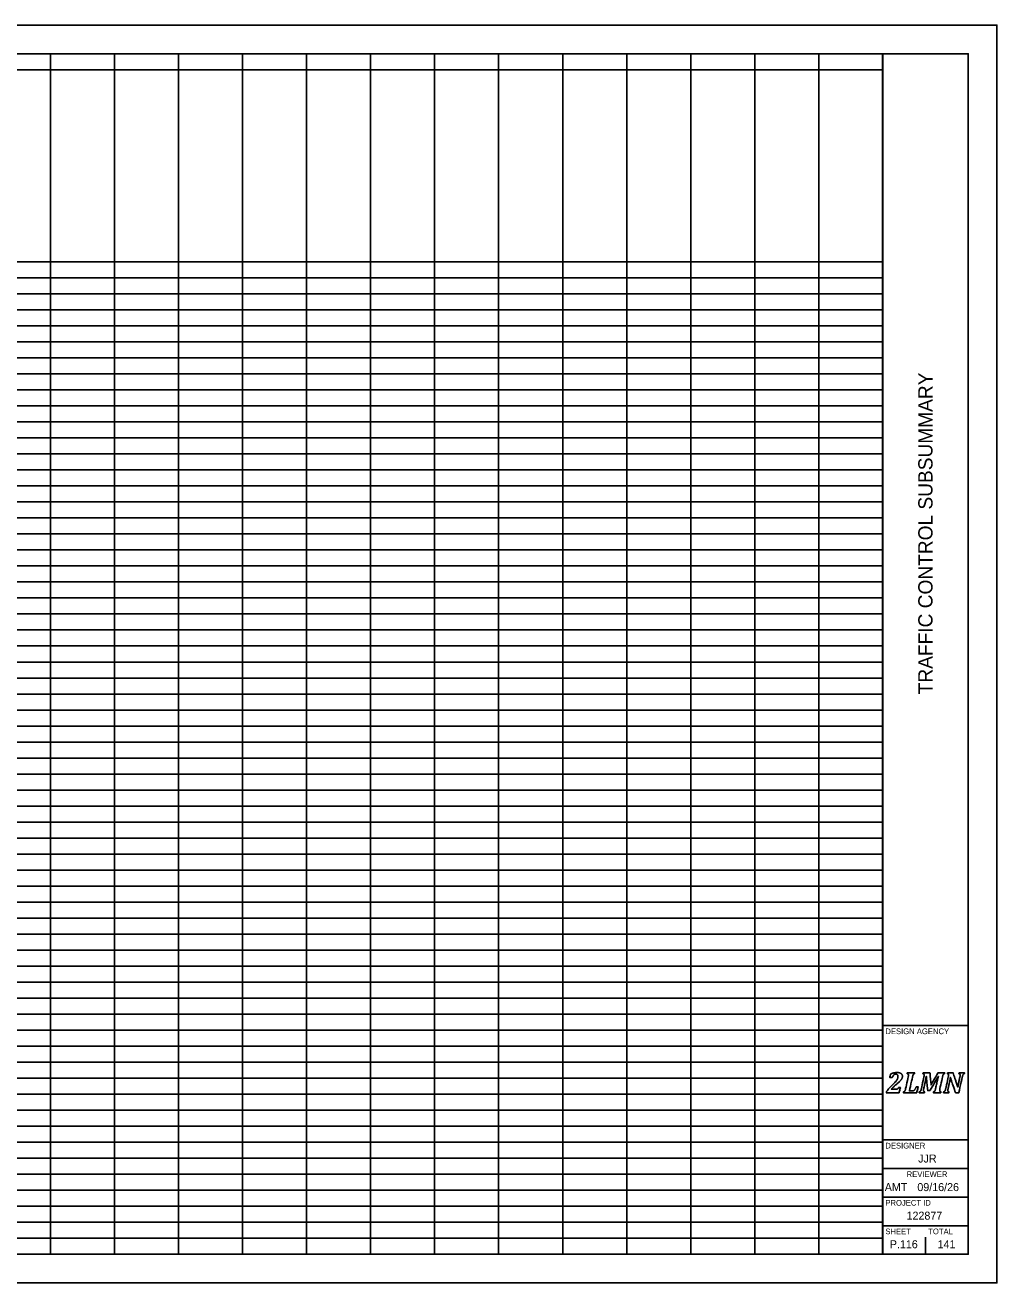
# Model space of a CAD drawing. Extents: x 0 to 34, y 0 to 22.
# Drawn here: x 17 to 34, y 0 to 22 of the extents above; entities that cross this region are included whole.
import ezdxf

# ---------------------------------------------------------------- set-up
doc = ezdxf.new("R2010")
doc.units = 0
for name, color, linetype in [('SH_Border', 7, 'Continuous'), ('SH_Cut_Line', 7, 'Continuous'), ('SH_Data', 7, 'Continuous'), ('SH_Text', 7, 'Continuous')]:
    doc.layers.add(name, color=color, linetype=linetype)

msp = doc.modelspace()

# ---------------------------------------------------------------- linework, layer by layer
at = {"layer": 'SH_Border'}
for p, q in [((32, 0.5), (32, 21.5)), ((32, 4.5), (33.5, 4.5)), ((32, 2.5), (33.5, 2.5)), ((32, 2), (33.5, 2)), ((32, 1.5), (33.5, 1.5)), ((32, 1), (33.5, 1))]:
    msp.add_line(p, q, dxfattribs=at)
msp.add_lwpolyline([(1.5, 21.5), (33.5, 21.5), (33.5, 0.5), (1.5, 0.5)], close=True, dxfattribs=at)
at = {"layer": 'SH_Cut_Line'}
msp.add_lwpolyline([(0, 0), (34, 0), (34, 22), (0, 22)], close=True, dxfattribs=at)
at = {"layer": 'SH_Data'}
for p, q in [((32.75, 3.5), (32.75, 3.5)), ((32.375, 0.675), (32.375, 0.675)), ((32.75, 0.5), (32.75, 0.8))]:
    msp.add_line(p, q, dxfattribs=at)
for points in [[(32.237, 3.388), (32.246, 3.388), (32.253, 3.389), (32.258, 3.39), (32.263, 3.392), (32.267, 3.394), (32.27, 3.397), (32.273, 3.401), (32.277, 3.408), (32.281, 3.417), (32.281, 3.417), (32.312, 3.417), (32.312, 3.417), (32.312, 3.417), (32.29, 3.326), (32.29, 3.326), (32.29, 3.326), (32.066, 3.326), (32.066, 3.326), (32.066, 3.326), (32.069, 3.343), (32.069, 3.343), (32.078, 3.358), (32.091, 3.375), (32.106, 3.394), (32.122, 3.412), (32.144, 3.435), (32.172, 3.462), (32.197, 3.486), (32.217, 3.506), (32.23, 3.521), (32.243, 3.537), (32.253, 3.551), (32.259, 3.566), (32.266, 3.58), (32.269, 3.595), (32.269, 3.61), (32.269, 3.622), (32.266, 3.632), (32.26, 3.64), (32.253, 3.647), (32.245, 3.65), (32.234, 3.65), (32.22, 3.65), (32.208, 3.646), (32.198, 3.636), (32.188, 3.627), (32.18, 3.613), (32.172, 3.593), (32.172, 3.593), (32.126, 3.593), (32.126, 3.593), (32.126, 3.593), (32.14, 3.654), (32.14, 3.654), (32.166, 3.663), (32.188, 3.669), (32.205, 3.673), (32.223, 3.676), (32.24, 3.678), (32.258, 3.678), (32.278, 3.678), (32.295, 3.675), (32.309, 3.669), (32.322, 3.664), (32.332, 3.656), (32.339, 3.646), (32.345, 3.637), (32.348, 3.626), (32.348, 3.613), (32.348, 3.602), (32.346, 3.591), (32.342, 3.581), (32.339, 3.571), (32.333, 3.56), (32.324, 3.549), (32.315, 3.539), (32.304, 3.526), (32.289, 3.513), (32.275, 3.499), (32.254, 3.482), (32.228, 3.46), (32.216, 3.45), (32.202, 3.438), (32.188, 3.425), (32.174, 3.412), (32.162, 3.4), (32.154, 3.391), (32.154, 3.391), (32.153, 3.388), (32.153, 3.388), (32.153, 3.388), (32.237, 3.388), (32.237, 3.388)], [(32.237, 3.388), (32.237, 3.388), (32.153, 3.388), (32.153, 3.388), (32.153, 3.388), (32.154, 3.391), (32.154, 3.391), (32.162, 3.4), (32.174, 3.412), (32.188, 3.425), (32.202, 3.438), (32.216, 3.45), (32.228, 3.46), (32.254, 3.482), (32.275, 3.499), (32.289, 3.513), (32.304, 3.526), (32.315, 3.539), (32.324, 3.549), (32.333, 3.56), (32.339, 3.571), (32.342, 3.581), (32.346, 3.591), (32.348, 3.602), (32.348, 3.613), (32.348, 3.626), (32.345, 3.637), (32.339, 3.646), (32.332, 3.656), (32.322, 3.664), (32.309, 3.669), (32.295, 3.675), (32.278, 3.678), (32.258, 3.678), (32.24, 3.678), (32.223, 3.676), (32.205, 3.673), (32.188, 3.669), (32.166, 3.663), (32.14, 3.654), (32.14, 3.654), (32.126, 3.593), (32.126, 3.593), (32.126, 3.593), (32.172, 3.593), (32.172, 3.593), (32.18, 3.613), (32.188, 3.627), (32.198, 3.636), (32.208, 3.646), (32.22, 3.65), (32.234, 3.65), (32.245, 3.65), (32.253, 3.647), (32.26, 3.64), (32.266, 3.632), (32.269, 3.622), (32.269, 3.61), (32.269, 3.595), (32.266, 3.58), (32.259, 3.566), (32.253, 3.551), (32.243, 3.537), (32.23, 3.521), (32.217, 3.506), (32.197, 3.486), (32.172, 3.462), (32.144, 3.435), (32.122, 3.412), (32.106, 3.394), (32.091, 3.375), (32.078, 3.358), (32.069, 3.343), (32.069, 3.343), (32.066, 3.326), (32.066, 3.326), (32.066, 3.326), (32.29, 3.326), (32.29, 3.326), (32.29, 3.326), (32.312, 3.417), (32.312, 3.417), (32.312, 3.417), (32.281, 3.417), (32.281, 3.417), (32.277, 3.408), (32.273, 3.401), (32.27, 3.397), (32.267, 3.394), (32.263, 3.392), (32.258, 3.39), (32.253, 3.389), (32.246, 3.388), (32.237, 3.388)], [(32.518, 3.356), (32.527, 3.356), (32.533, 3.357), (32.538, 3.358), (32.542, 3.36), (32.546, 3.362), (32.55, 3.365), (32.554, 3.368), (32.558, 3.372), (32.562, 3.377), (32.567, 3.382), (32.571, 3.388), (32.576, 3.397), (32.58, 3.405), (32.585, 3.415), (32.589, 3.427), (32.589, 3.427), (32.624, 3.427), (32.624, 3.427), (32.624, 3.427), (32.598, 3.326), (32.598, 3.326), (32.598, 3.326), (32.365, 3.326), (32.365, 3.326), (32.365, 3.326), (32.369, 3.343), (32.369, 3.343), (32.376, 3.345), (32.381, 3.348), (32.385, 3.351), (32.389, 3.355), (32.392, 3.36), (32.395, 3.366), (32.398, 3.373), (32.4, 3.382), (32.403, 3.395), (32.403, 3.395), (32.449, 3.605), (32.449, 3.605), (32.452, 3.615), (32.453, 3.625), (32.453, 3.635), (32.453, 3.642), (32.451, 3.647), (32.448, 3.651), (32.444, 3.654), (32.439, 3.656), (32.432, 3.657), (32.432, 3.657), (32.435, 3.674), (32.435, 3.674), (32.435, 3.674), (32.563, 3.674), (32.563, 3.674), (32.563, 3.674), (32.559, 3.657), (32.559, 3.657), (32.552, 3.655), (32.547, 3.652), (32.543, 3.649), (32.539, 3.645), (32.536, 3.64), (32.533, 3.634), (32.531, 3.627), (32.528, 3.618), (32.525, 3.605), (32.525, 3.605), (32.47, 3.356), (32.47, 3.356), (32.47, 3.356), (32.518, 3.356), (32.518, 3.356)], [(32.518, 3.356), (32.518, 3.356), (32.47, 3.356), (32.47, 3.356), (32.47, 3.356), (32.525, 3.605), (32.525, 3.605), (32.528, 3.618), (32.531, 3.627), (32.533, 3.634), (32.536, 3.64), (32.539, 3.645), (32.543, 3.649), (32.547, 3.652), (32.552, 3.655), (32.559, 3.657), (32.559, 3.657), (32.563, 3.674), (32.563, 3.674), (32.563, 3.674), (32.435, 3.674), (32.435, 3.674), (32.435, 3.674), (32.432, 3.657), (32.432, 3.657), (32.439, 3.656), (32.444, 3.654), (32.448, 3.651), (32.451, 3.647), (32.453, 3.642), (32.453, 3.635), (32.453, 3.625), (32.452, 3.615), (32.449, 3.605), (32.449, 3.605), (32.403, 3.395), (32.403, 3.395), (32.4, 3.382), (32.398, 3.373), (32.395, 3.366), (32.392, 3.36), (32.389, 3.355), (32.385, 3.351), (32.381, 3.348), (32.376, 3.345), (32.369, 3.343), (32.369, 3.343), (32.365, 3.326), (32.365, 3.326), (32.365, 3.326), (32.598, 3.326), (32.598, 3.326), (32.598, 3.326), (32.624, 3.427), (32.624, 3.427), (32.624, 3.427), (32.589, 3.427), (32.589, 3.427), (32.585, 3.415), (32.58, 3.405), (32.576, 3.397), (32.571, 3.388), (32.567, 3.382), (32.562, 3.377), (32.558, 3.372), (32.554, 3.368), (32.55, 3.365), (32.546, 3.362), (32.542, 3.36), (32.538, 3.358), (32.533, 3.357), (32.527, 3.356), (32.518, 3.356)], [(32.829, 3.674), (32.829, 3.674), (32.849, 3.461), (32.849, 3.461), (32.849, 3.461), (32.969, 3.674), (32.969, 3.674), (32.969, 3.674), (33.087, 3.674), (33.087, 3.674), (33.087, 3.674), (33.084, 3.657), (33.084, 3.657), (33.077, 3.655), (33.071, 3.652), (33.067, 3.649), (33.064, 3.645), (33.06, 3.64), (33.058, 3.634), (33.055, 3.627), (33.052, 3.618), (33.05, 3.605), (33.05, 3.605), (33.003, 3.395), (33.003, 3.395), (33.002, 3.39), (33.002, 3.387), (33.001, 3.384), (33.001, 3.382), (33.001, 3.379), (33, 3.376), (33, 3.373), (33, 3.369), (33, 3.365), (33, 3.358), (33.002, 3.353), (33.005, 3.349), (33.008, 3.346), (33.014, 3.344), (33.021, 3.343), (33.021, 3.343), (33.018, 3.326), (33.018, 3.326), (33.018, 3.326), (32.89, 3.326), (32.89, 3.326), (32.89, 3.326), (32.893, 3.343), (32.893, 3.343), (32.9, 3.345), (32.906, 3.348), (32.91, 3.351), (32.914, 3.355), (32.917, 3.36), (32.919, 3.366), (32.922, 3.373), (32.925, 3.382), (32.928, 3.395), (32.928, 3.395), (32.951, 3.502), (32.951, 3.502), (32.954, 3.513), (32.957, 3.529), (32.962, 3.548), (32.967, 3.568), (32.972, 3.588), (32.978, 3.609), (32.978, 3.609), (32.973, 3.609), (32.973, 3.609), (32.965, 3.594), (32.957, 3.579), (32.948, 3.563), (32.948, 3.563), (32.833, 3.364), (32.833, 3.364), (32.833, 3.364), (32.792, 3.364), (32.792, 3.364), (32.792, 3.364), (32.775, 3.518), (32.775, 3.518), (32.773, 3.537), (32.772, 3.554), (32.77, 3.569), (32.769, 3.583), (32.768, 3.597), (32.768, 3.611), (32.768, 3.611), (32.764, 3.611), (32.764, 3.611), (32.761, 3.596), (32.758, 3.578), (32.755, 3.558), (32.751, 3.538), (32.747, 3.521), (32.744, 3.507), (32.744, 3.507), (32.72, 3.395), (32.72, 3.395), (32.719, 3.39), (32.718, 3.387), (32.718, 3.384), (32.717, 3.382), (32.717, 3.379), (32.717, 3.376), (32.717, 3.373), (32.716, 3.369), (32.716, 3.365), (32.716, 3.358), (32.718, 3.353), (32.721, 3.349), (32.725, 3.346), (32.73, 3.344), (32.738, 3.343), (32.738, 3.343), (32.734, 3.326), (32.734, 3.326), (32.734, 3.326), (32.641, 3.326), (32.641, 3.326), (32.641, 3.326), (32.644, 3.343), (32.644, 3.343), (32.651, 3.345), (32.657, 3.348), (32.661, 3.351), (32.665, 3.355), (32.668, 3.36), (32.67, 3.366), (32.673, 3.373), (32.676, 3.382), (32.679, 3.395), (32.679, 3.395), (32.725, 3.605), (32.725, 3.605), (32.727, 3.615), (32.728, 3.625), (32.728, 3.635), (32.728, 3.642), (32.727, 3.647), (32.723, 3.651), (32.72, 3.654), (32.715, 3.656), (32.707, 3.657), (32.707, 3.657), (32.711, 3.674), (32.711, 3.674), (32.711, 3.674), (32.829, 3.674), (32.829, 3.674)], [(32.829, 3.674), (32.829, 3.674), (32.711, 3.674), (32.711, 3.674), (32.711, 3.674), (32.707, 3.657), (32.707, 3.657), (32.715, 3.656), (32.72, 3.654), (32.723, 3.651), (32.727, 3.647), (32.728, 3.642), (32.728, 3.635), (32.728, 3.625), (32.727, 3.615), (32.725, 3.605), (32.725, 3.605), (32.679, 3.395), (32.679, 3.395), (32.676, 3.382), (32.673, 3.373), (32.67, 3.366), (32.668, 3.36), (32.665, 3.355), (32.661, 3.351), (32.657, 3.348), (32.651, 3.345), (32.644, 3.343), (32.644, 3.343), (32.641, 3.326), (32.641, 3.326), (32.641, 3.326), (32.734, 3.326), (32.734, 3.326), (32.734, 3.326), (32.738, 3.343), (32.738, 3.343), (32.73, 3.344), (32.725, 3.346), (32.721, 3.349), (32.718, 3.353), (32.716, 3.358), (32.716, 3.365), (32.716, 3.369), (32.717, 3.373), (32.717, 3.376), (32.717, 3.379), (32.717, 3.382), (32.718, 3.384), (32.718, 3.387), (32.719, 3.39), (32.72, 3.395), (32.72, 3.395), (32.744, 3.507), (32.744, 3.507), (32.747, 3.521), (32.751, 3.538), (32.755, 3.558), (32.758, 3.578), (32.761, 3.596), (32.764, 3.611), (32.764, 3.611), (32.768, 3.611), (32.768, 3.611), (32.768, 3.597), (32.769, 3.583), (32.77, 3.569), (32.772, 3.554), (32.773, 3.537), (32.775, 3.518), (32.775, 3.518), (32.792, 3.364), (32.792, 3.364), (32.792, 3.364), (32.833, 3.364), (32.833, 3.364), (32.833, 3.364), (32.948, 3.563), (32.948, 3.563), (32.957, 3.579), (32.965, 3.594), (32.973, 3.609), (32.973, 3.609), (32.978, 3.609), (32.978, 3.609), (32.972, 3.588), (32.967, 3.568), (32.962, 3.548), (32.957, 3.529), (32.954, 3.513), (32.951, 3.502), (32.951, 3.502), (32.928, 3.395), (32.928, 3.395), (32.925, 3.382), (32.922, 3.373), (32.919, 3.366), (32.917, 3.36), (32.914, 3.355), (32.91, 3.351), (32.906, 3.348), (32.9, 3.345), (32.893, 3.343), (32.893, 3.343), (32.89, 3.326), (32.89, 3.326), (32.89, 3.326), (33.018, 3.326), (33.018, 3.326), (33.018, 3.326), (33.021, 3.343), (33.021, 3.343), (33.014, 3.344), (33.008, 3.346), (33.005, 3.349), (33.002, 3.353), (33, 3.358), (33, 3.365), (33, 3.369), (33, 3.373), (33, 3.376), (33.001, 3.379), (33.001, 3.382), (33.001, 3.384), (33.002, 3.387), (33.002, 3.39), (33.003, 3.395), (33.003, 3.395), (33.05, 3.605), (33.05, 3.605), (33.052, 3.618), (33.055, 3.627), (33.058, 3.634), (33.06, 3.64), (33.064, 3.645), (33.067, 3.649), (33.071, 3.652), (33.077, 3.655), (33.084, 3.657), (33.084, 3.657), (33.087, 3.674), (33.087, 3.674), (33.087, 3.674), (32.969, 3.674), (32.969, 3.674), (32.969, 3.674), (32.849, 3.461), (32.849, 3.461), (32.849, 3.461), (32.829, 3.674), (32.829, 3.674)], [(33.137, 3.674), (33.137, 3.674), (33.234, 3.674), (33.234, 3.674), (33.234, 3.674), (33.283, 3.53), (33.283, 3.53), (33.296, 3.49), (33.307, 3.456), (33.315, 3.426), (33.315, 3.426), (33.318, 3.426), (33.318, 3.426), (33.323, 3.455), (33.329, 3.488), (33.337, 3.523), (33.337, 3.523), (33.355, 3.605), (33.355, 3.605), (33.357, 3.615), (33.358, 3.625), (33.358, 3.635), (33.358, 3.642), (33.357, 3.647), (33.353, 3.651), (33.35, 3.654), (33.345, 3.656), (33.337, 3.657), (33.337, 3.657), (33.341, 3.674), (33.341, 3.674), (33.341, 3.674), (33.434, 3.674), (33.434, 3.674), (33.434, 3.674), (33.431, 3.657), (33.431, 3.657), (33.424, 3.655), (33.418, 3.652), (33.414, 3.649), (33.41, 3.645), (33.407, 3.64), (33.405, 3.634), (33.402, 3.627), (33.399, 3.618), (33.396, 3.605), (33.396, 3.605), (33.335, 3.326), (33.335, 3.326), (33.335, 3.326), (33.277, 3.326), (33.277, 3.326), (33.277, 3.326), (33.216, 3.504), (33.216, 3.504), (33.211, 3.518), (33.207, 3.531), (33.204, 3.543), (33.2, 3.556), (33.195, 3.571), (33.19, 3.59), (33.19, 3.59), (33.186, 3.59), (33.186, 3.59), (33.185, 3.579), (33.182, 3.563), (33.179, 3.543), (33.175, 3.523), (33.17, 3.501), (33.165, 3.478), (33.165, 3.478), (33.147, 3.395), (33.147, 3.395), (33.146, 3.39), (33.145, 3.387), (33.145, 3.384), (33.144, 3.382), (33.144, 3.379), (33.144, 3.376), (33.143, 3.373), (33.143, 3.369), (33.143, 3.365), (33.143, 3.358), (33.145, 3.353), (33.148, 3.349), (33.152, 3.346), (33.157, 3.344), (33.164, 3.343), (33.164, 3.343), (33.161, 3.326), (33.161, 3.326), (33.161, 3.326), (33.067, 3.326), (33.067, 3.326), (33.067, 3.326), (33.071, 3.343), (33.071, 3.343), (33.078, 3.345), (33.083, 3.348), (33.087, 3.351), (33.091, 3.355), (33.094, 3.36), (33.097, 3.366), (33.1, 3.373), (33.102, 3.382), (33.105, 3.395), (33.105, 3.395), (33.151, 3.605), (33.151, 3.605), (33.154, 3.615), (33.155, 3.625), (33.155, 3.635), (33.155, 3.642), (33.153, 3.647), (33.15, 3.651), (33.146, 3.654), (33.141, 3.656), (33.134, 3.657), (33.134, 3.657), (33.137, 3.674), (33.137, 3.674)], [(33.137, 3.674), (33.137, 3.674), (33.134, 3.657), (33.134, 3.657), (33.141, 3.656), (33.146, 3.654), (33.15, 3.651), (33.153, 3.647), (33.155, 3.642), (33.155, 3.635), (33.155, 3.625), (33.154, 3.615), (33.151, 3.605), (33.151, 3.605), (33.105, 3.395), (33.105, 3.395), (33.102, 3.382), (33.1, 3.373), (33.097, 3.366), (33.094, 3.36), (33.091, 3.355), (33.087, 3.351), (33.083, 3.348), (33.078, 3.345), (33.071, 3.343), (33.071, 3.343), (33.067, 3.326), (33.067, 3.326), (33.067, 3.326), (33.161, 3.326), (33.161, 3.326), (33.161, 3.326), (33.164, 3.343), (33.164, 3.343), (33.157, 3.344), (33.152, 3.346), (33.148, 3.349), (33.145, 3.353), (33.143, 3.358), (33.143, 3.365), (33.143, 3.369), (33.143, 3.373), (33.144, 3.376), (33.144, 3.379), (33.144, 3.382), (33.145, 3.384), (33.145, 3.387), (33.146, 3.39), (33.147, 3.395), (33.147, 3.395), (33.165, 3.478), (33.165, 3.478), (33.17, 3.501), (33.175, 3.523), (33.179, 3.543), (33.182, 3.563), (33.185, 3.579), (33.186, 3.59), (33.186, 3.59), (33.19, 3.59), (33.19, 3.59), (33.195, 3.571), (33.2, 3.556), (33.204, 3.543), (33.207, 3.531), (33.211, 3.518), (33.216, 3.504), (33.216, 3.504), (33.277, 3.326), (33.277, 3.326), (33.277, 3.326), (33.335, 3.326), (33.335, 3.326), (33.335, 3.326), (33.396, 3.605), (33.396, 3.605), (33.399, 3.618), (33.402, 3.627), (33.405, 3.634), (33.407, 3.64), (33.41, 3.645), (33.414, 3.649), (33.418, 3.652), (33.424, 3.655), (33.431, 3.657), (33.431, 3.657), (33.434, 3.674), (33.434, 3.674), (33.434, 3.674), (33.341, 3.674), (33.341, 3.674), (33.341, 3.674), (33.337, 3.657), (33.337, 3.657), (33.345, 3.656), (33.35, 3.654), (33.353, 3.651), (33.357, 3.647), (33.358, 3.642), (33.358, 3.635), (33.358, 3.625), (33.357, 3.615), (33.355, 3.605), (33.355, 3.605), (33.337, 3.523), (33.337, 3.523), (33.329, 3.488), (33.323, 3.455), (33.318, 3.426), (33.318, 3.426), (33.315, 3.426), (33.315, 3.426), (33.307, 3.456), (33.296, 3.49), (33.283, 3.53), (33.283, 3.53), (33.234, 3.674), (33.234, 3.674), (33.234, 3.674), (33.137, 3.674), (33.137, 3.674)]]:
    msp.add_open_spline(points, degree=3, dxfattribs=at)
at = {"layer": 'SH_Text'}
for p, q in [((1.5, 21.5), (32.004, 21.5)), ((17.444, 21.5), (17.444, 0.5)), ((18.564, 21.5), (18.564, 0.5)), ((19.684, 21.5), (19.684, 0.5)), ((20.804, 21.5), (20.804, 0.5)), ((21.924, 21.5), (21.924, 0.5)), ((23.044, 21.5), (23.044, 0.5)), ((24.164, 21.5), (24.164, 0.5)), ((25.284, 21.5), (25.284, 0.5)), ((26.404, 21.5), (26.404, 0.5)), ((27.524, 21.5), (27.524, 0.5)), ((28.644, 21.5), (28.644, 0.5)), ((29.764, 21.5), (29.764, 0.5)), ((30.884, 21.5), (30.884, 0.5)), ((32.004, 21.5), (32.004, 0.5)), ((9.604, 21.22), (32.004, 21.22)), ((9.604, 17.86), (32.004, 17.86)), ((1.5, 17.58), (32.004, 17.58)), ((1.5, 17.3), (32.004, 17.3)), ((1.5, 17.02), (32.004, 17.02)), ((1.5, 16.74), (32.004, 16.74)), ((1.5, 16.46), (32.004, 16.46)), ((1.5, 16.18), (32.004, 16.18)), ((1.5, 15.9), (32.004, 15.9)), ((1.5, 15.62), (32.004, 15.62)), ((1.5, 15.34), (32.004, 15.34)), ((1.5, 15.06), (32.004, 15.06)), ((1.5, 14.78), (32.004, 14.78)), ((1.5, 14.5), (32.004, 14.5)), ((1.5, 14.22), (32.004, 14.22)), ((1.5, 13.94), (32.004, 13.94)), ((1.5, 13.66), (32.004, 13.66)), ((1.5, 13.38), (32.004, 13.38)), ((1.5, 13.1), (32.004, 13.1)), ((1.5, 12.82), (32.004, 12.82)), ((1.5, 12.54), (32.004, 12.54)), ((1.5, 12.26), (32.004, 12.26)), ((1.5, 11.98), (32.004, 11.98)), ((1.5, 11.7), (32.004, 11.7)), ((1.5, 11.42), (32.004, 11.42)), ((1.5, 11.14), (32.004, 11.14)), ((1.5, 10.86), (32.004, 10.86)), ((1.5, 10.58), (32.004, 10.58)), ((1.5, 10.3), (32.004, 10.3)), ((1.5, 10.02), (32.004, 10.02)), ((1.5, 9.74), (32.004, 9.74)), ((1.5, 9.46), (32.004, 9.46)), ((1.5, 9.18), (32.004, 9.18)), ((1.5, 8.9), (32.004, 8.9)), ((1.5, 8.62), (32.004, 8.62)), ((1.5, 8.34), (32.004, 8.34)), ((1.5, 8.06), (32.004, 8.06)), ((1.5, 7.78), (32.004, 7.78)), ((1.5, 7.5), (32.004, 7.5)), ((1.5, 7.22), (32.004, 7.22)), ((1.5, 6.94), (32.004, 6.94)), ((1.5, 6.66), (32.004, 6.66)), ((1.5, 6.38), (32.004, 6.38)), ((1.5, 6.1), (32.004, 6.1)), ((1.5, 5.82), (32.004, 5.82)), ((1.5, 5.54), (32.004, 5.54)), ((1.5, 5.26), (32.004, 5.26)), ((1.5, 4.98), (32.004, 4.98)), ((1.5, 4.7), (32.004, 4.7)), ((1.5, 4.42), (32.004, 4.42)), ((1.5, 4.14), (32.004, 4.14)), ((1.5, 3.86), (32.004, 3.86)), ((1.5, 3.58), (32.004, 3.58)), ((1.5, 3.3), (32.004, 3.3)), ((1.5, 3.02), (32.004, 3.02)), ((1.5, 2.74), (32.004, 2.74)), ((1.5, 2.46), (32.004, 2.46)), ((1.5, 2.18), (32.004, 2.18)), ((1.5, 1.9), (32.004, 1.9)), ((1.5, 1.62), (32.004, 1.62)), ((1.5, 1.34), (32.004, 1.34)), ((1.5, 1.06), (32.004, 1.06)), ((1.5, 0.78), (32.004, 0.78)), ((1.5, 0.5), (32.004, 0.5))]:
    msp.add_line(p, q, dxfattribs=at)

# ---------------------------------------------------------------- texts
at = {"layer": 'SH_Data'}
msp.add_text('TRAFFIC CONTROL SUBSUMMARY', height=0.25, rotation=90, dxfattribs=at).set_placement((32.875, 10.295))
for s, height, p in [('DESIGN AGENCY', 0.1, (32.05, 4.35)), ('DESIGNER', 0.1, (32.05, 2.35)), ('JJR', 0.14, (32.624, 2.105)), ('REVIEWER', 0.1, (32.422, 1.85)), ('AMT', 0.14, (32.039, 1.605)), ('09/16/26', 0.14, (32.609, 1.605)), ('PROJECT ID', 0.1, (32.05, 1.35)), ('122877', 0.14, (32.42, 1.105)), ('SHEET', 0.1, (32.05, 0.85)), ('TOTAL', 0.1, (32.8, 0.85)), ('P.116', 0.14, (32.127, 0.605)), ('141', 0.14, (32.963, 0.605))]:
    msp.add_text(s, height=height, dxfattribs=at).set_placement(p)

doc.saveas('drawing.dxf')
